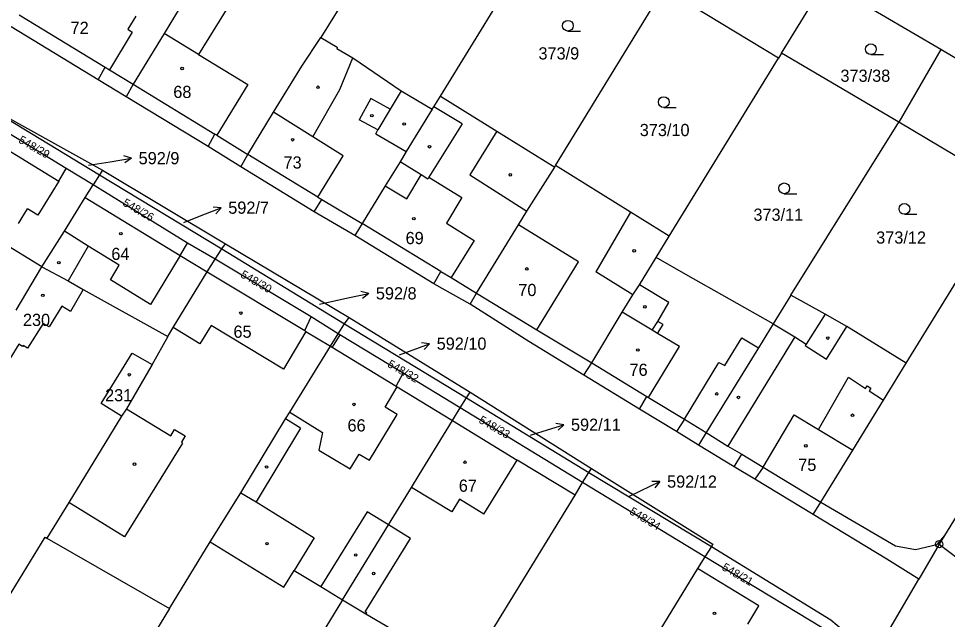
# Model space of a CAD drawing. Extents: x -758582 to -751794, y -998770 to -994350.
# Drawn here: x -754377.8 to -754248.1, y -997016.7 to -996932.8 of the extents above; entities that cross this region are included whole.
import ezdxf

# ---------------------------------------------------------------- set-up
doc = ezdxf.new("R2010")
doc.units = 0
for name, color, linetype in [('Hranice parcel', 7, 'Continuous'), ('Parcelní čísla', 7, 'Continuous'), ('Pop  PČ popisy', 7, 'Continuous'), ('Vnitřní kresba', 7, 'Continuous'), ('Značky bodu BP', 7, 'Continuous'), ('Značky budov', 7, 'Continuous'), ('Značky kultur', 7, 'Continuous')]:
    doc.layers.add(name, color=color, linetype=linetype)

msp = doc.modelspace()

# ---------------------------------------------------------------- linework, layer by layer
at = {"layer": 'Hranice parcel'}
for p, q in [((-754318.92, -996943.63), (-754303.3, -996918.26)), ((-754271.31, -996937.63), (-754265.19, -996927.65)), ((-754249.07, -996937.1), (-754265.19, -996927.65)), ((-754302.83, -996953.32), (-754287.72, -996928.63)), ((-754271.74, -996938.33), (-754287.72, -996928.63)), ((-754249.07, -996937.1), (-754254.94, -996947.27)), ((-754232.94, -996946.73), (-754249.07, -996937.1)), ((-754286.99, -996963.15), (-754271.74, -996938.33)), ((-754271.31, -996937.63), (-754271.74, -996938.33)), ((-754254.94, -996947.27), (-754271.31, -996937.63)), ((-754383.67, -996944.19), (-754366.1, -996953.94)), ((-754383.67, -996944.19), (-754366.52, -996954.61)), ((-754269.98, -996971.41), (-754254.94, -996947.27)), ((-754239.04, -996956.72), (-754254.94, -996947.27)), ((-754366.1, -996953.94), (-754366.52, -996954.61)), ((-754366.1, -996953.94), (-754348.94, -996964.22)), ((-754302.96, -996953.53), (-754302.83, -996953.32)), ((-754366.52, -996954.61), (-754367.41, -996956.01)), ((-754366.52, -996954.61), (-754349.44, -996964.96)), ((-754253.88, -996980.88), (-754239.04, -996956.72)), ((-754288.82, -996966.16), (-754286.99, -996963.15)), ((-754349.44, -996964.96), (-754348.94, -996964.22)), ((-754348.94, -996964.22), (-754331.64, -996974.52)), ((-754350.35, -996966.4), (-754349.44, -996964.96)), ((-754349.44, -996964.96), (-754332.29, -996975.4)), ((-754378.16, -996973.49), (-754374.58, -996967.43)), ((-754368.79, -996970.6), (-754356.99, -996977.19)), ((-754269.98, -996971.41), (-754272.44, -996975.39)), ((-754332.29, -996975.4), (-754331.64, -996974.52)), ((-754331.64, -996974.52), (-754314.77, -996984.96)), ((-754333.17, -996976.81), (-754332.29, -996975.4)), ((-754332.29, -996975.4), (-754315.29, -996985.75)), ((-754356.99, -996977.19), (-754359.18, -996981.08)), ((-754315.29, -996985.75), (-754314.77, -996984.96)), ((-754314.77, -996984.96), (-754297.84, -996995.61)), ((-754316.16, -996987.15), (-754315.29, -996985.75)), ((-754315.29, -996985.75), (-754298.18, -996996.15)), ((-754299.06, -996997.55), (-754316.16, -996987.15)), ((-754298.18, -996996.15), (-754297.84, -996995.61)), ((-754299.06, -996997.55), (-754298.18, -996996.15)), ((-754298.18, -996996.15), (-754281.08, -997006.49)), ((-754281.98, -997007.92), (-754299.06, -996997.55)), ((-754373.87, -997005.32), (-754356.72, -997015.17)), ((-754356.72, -997015.17), (-754351.05, -997005.83)), ((-754281.08, -997006.49), (-754281.98, -997007.92)), ((-754258.68, -997022.29), (-754252.12, -997011.03)), ((-754332.57, -997013.92), (-754336.66, -997020.59)), ((-754356.72, -997015.17), (-754373.8, -997042.91))]:
    msp.add_line(p, q, dxfattribs=at)
for points in [[(-754323.36, -996915.29), (-754327.65, -996922.3), (-754327.53, -996922.34), (-754335.61, -996935.42)], [(-754345.53, -996915.8), (-754345.9, -996916.39), (-754346.91, -996918.02), (-754347.35, -996918.73), (-754349.19, -996921.79), (-754355.4, -996931.43), (-754357.5, -996934.88), (-754361.81, -996941.97), (-754362.79, -996943.71)], [(-754362.79, -996943.71), (-754366.69, -996941.33), (-754378.83, -996933.97)], [(-754346.77, -996953.49), (-754345.82, -996951.75), (-754342.21, -996945.87), (-754338.26, -996939.44), (-754335.61, -996935.42)], [(-754335.61, -996935.42), (-754333.31, -996936.79), (-754333.39, -996936.95), (-754331.15, -996938.27), (-754324.4, -996942.87), (-754320.06, -996945.44)], [(-754346.77, -996953.49), (-754351.36, -996950.67), (-754362.79, -996943.71)], [(-754320.06, -996945.44), (-754319.82, -996945.1), (-754318.92, -996943.63)], [(-754318.92, -996943.63), (-754311.02, -996948.53), (-754302.96, -996953.53)], [(-754367.41, -996956.01), (-754371.18, -996953.71), (-754384.54, -996945.57)], [(-754320.06, -996945.44), (-754323.71, -996951.35), (-754324.53, -996952.81), (-754326.63, -996956.13), (-754329.83, -996961.39), (-754330.85, -996963.1)], [(-754330.85, -996963.1), (-754336.52, -996959.75), (-754346.77, -996953.49)], [(-754314.75, -996972.65), (-754313.87, -996971.12), (-754308, -996961.6), (-754306.83, -996959.7), (-754302.96, -996953.53)], [(-754286.99, -996963.15), (-754292.38, -996959.82), (-754302.83, -996953.32)], [(-754218.11, -996955.35), (-754218.17, -996955.44), (-754248.54, -997004.94), (-754249.29, -997006.16), (-754252.12, -997011.03)], [(-754374.58, -996967.43), (-754371.38, -996962.49), (-754368.51, -996957.75), (-754367.41, -996956.01)], [(-754350.35, -996966.4), (-754354.23, -996964.15), (-754367.41, -996956.01)], [(-754314.75, -996972.65), (-754319.85, -996969.81), (-754330.85, -996963.1)], [(-754356.99, -996977.19), (-754356.24, -996975.93), (-754351.46, -996968.17), (-754350.35, -996966.4)], [(-754333.17, -996976.81), (-754336.96, -996974.44), (-754350.35, -996966.4)], [(-754298.88, -996982.59), (-754297.8, -996980.84), (-754293.55, -996973.77), (-754292.06, -996971.34), (-754291.12, -996969.95), (-754288.82, -996966.16)], [(-754272.44, -996975.39), (-754284.67, -996968.5), (-754288.82, -996966.16)], [(-754374.58, -996967.43), (-754370.89, -996969.4), (-754368.79, -996970.6)], [(-754368.79, -996970.6), (-754370.57, -996973.68), (-754371.79, -996972.96), (-754373.55, -996975.81), (-754374.38, -996975.35), (-754376.57, -996978.82), (-754377.19, -996978.44), (-754377.27, -996978.55), (-754377.78, -996978.26), (-754379.02, -996980.29), (-754381.39, -996978.8)], [(-754253.88, -996980.88), (-754262.19, -996975.76), (-754265.19, -996974.04), (-754269.98, -996971.41)], [(-754298.88, -996982.59), (-754306.59, -996977.86), (-754314.75, -996972.65)], [(-754272.44, -996975.39), (-754274.53, -996978.77), (-754281.81, -996990.6), (-754282.89, -996992.33)], [(-754351.05, -997005.83), (-754346.8, -996999), (-754340.55, -996988.67), (-754339.93, -996987.73), (-754334.25, -996978.53), (-754333.17, -996976.81)], [(-754316.16, -996987.15), (-754324.11, -996982.3), (-754332.95, -996976.93), (-754333.17, -996976.81)], [(-754363.43, -996988.3), (-754366.29, -996986.52), (-754361.96, -996979.49), (-754359.18, -996981.08)], [(-754359.18, -996981.08), (-754362.74, -996987.29), (-754363.43, -996988.3)], [(-754266.86, -997002.01), (-754265.79, -997000.29), (-754261.34, -996993.04), (-754257.07, -996986.08), (-754253.88, -996980.88)], [(-754282.89, -996992.33), (-754285.94, -996990.45), (-754291.13, -996987.3), (-754298.88, -996982.59)], [(-754332.57, -997013.92), (-754326.17, -997003.48), (-754322.94, -996998.24), (-754321.9, -996996.49), (-754317.23, -996988.89), (-754316.16, -996987.15)], [(-754363.43, -996988.3), (-754370.81, -997000.35), (-754373.87, -997005.32)], [(-754266.86, -997002.01), (-754275.01, -996997.08), (-754277.91, -996995.35), (-754282.89, -996992.33)], [(-754297.84, -996995.61), (-754280.88, -997006.15), (-754281.08, -997006.49)], [(-754319.52, -997030.98), (-754300.11, -996999.31), (-754299.06, -996997.55)], [(-754252.12, -997011.03), (-754256.61, -997008.28), (-754266.86, -997002.01)], [(-754391.03, -997032.84), (-754374.11, -997005.21), (-754373.87, -997005.32)], [(-754351.05, -997005.83), (-754340.78, -997012.16), (-754339.33, -997009.82), (-754335.6, -997012.08), (-754332.57, -997013.92)], [(-754281.08, -997006.49), (-754264.39, -997016.71), (-754260.86, -997019.73), (-754258.68, -997022.29)], [(-754281.98, -997007.92), (-754283.01, -997009.56), (-754288.27, -997018.16), (-754295.28, -997029.61), (-754299.99, -997037.3), (-754300.15, -997037.64), (-754303.11, -997042.42), (-754306.17, -997047.33)], [(-754260.55, -997025.5), (-754261.83, -997020.13), (-754281.98, -997007.92)]]:
    msp.add_lwpolyline(points, dxfattribs=at)
at = {"layer": 'Pop  PČ popisy'}
for p, q in [((-754368.07, -996953.27), (-754365.01, -996952.77)), ((-754365.01, -996952.77), (-754362.05, -996952.3)), ((-754362.05, -996952.3), (-754363.11, -996951.96)), ((-754362.05, -996952.3), (-754362.96, -996952.95)), ((-754352.33, -996960.29), (-754349.53, -996959.21)), ((-754349.53, -996959.21), (-754350.64, -996959.11)), ((-754349.53, -996959.21), (-754350.28, -996960.04)), ((-754354.76, -996961.24), (-754352.33, -996960.29)), ((-754331.86, -996971.79), (-754328.93, -996971.17)), ((-754328.93, -996971.17), (-754330.01, -996970.88)), ((-754328.93, -996971.17), (-754329.8, -996971.86)), ((-754335.78, -996972.64), (-754331.86, -996971.79)), ((-754323.25, -996979.22), (-754320.43, -996978.19)), ((-754320.43, -996978.19), (-754321.54, -996978.07)), ((-754320.43, -996978.19), (-754321.2, -996979.01)), ((-754324.62, -996979.73), (-754323.25, -996979.22)), ((-754301.69, -996989.49), (-754302.79, -996989.31)), ((-754306.36, -996990.93), (-754304.56, -996990.37)), ((-754304.56, -996990.37), (-754301.69, -996989.49)), ((-754301.69, -996989.49), (-754302.5, -996990.26)), ((-754290.98, -996998.73), (-754288.28, -996997.41)), ((-754288.28, -996997.41), (-754289.4, -996997.4)), ((-754288.28, -996997.41), (-754288.96, -996998.3)), ((-754292.51, -996999.46), (-754290.98, -996998.73))]:
    msp.add_line(p, q, dxfattribs=at)
at = {"layer": 'Vnitřní kresba'}
for p, q in [((-754342.24, -996920.87), (-754352.68, -996937.8)), ((-754377.74, -996932.26), (-754365.71, -996939.59)), ((-754361.44, -996932.48), (-754362.56, -996934.29)), ((-754361.94, -996934.68), (-754365.13, -996939.94)), ((-754362.56, -996934.29), (-754361.94, -996934.68)), ((-754352.68, -996937.8), (-754357.5, -996934.88)), ((-754352.68, -996937.8), (-754345.79, -996941.98)), ((-754332.94, -996942.68), (-754331.15, -996938.27)), ((-754366.69, -996941.33), (-754365.71, -996939.59)), ((-754365.71, -996939.59), (-754365.13, -996939.94)), ((-754365.13, -996939.94), (-754361.81, -996941.97)), ((-754361.81, -996941.97), (-754350.41, -996948.91)), ((-754345.79, -996941.98), (-754350.15, -996949.06)), ((-754336.71, -996949.31), (-754332.94, -996942.68)), ((-754328.64, -996943.96), (-754330.25, -996946.91)), ((-754325.93, -996945.45), (-754328.64, -996943.96)), ((-754324.4, -996942.87), (-754325.93, -996945.45)), ((-754315.9, -996947.51), (-754319.82, -996945.1)), ((-754336.71, -996949.31), (-754342.21, -996945.87)), ((-754325.93, -996945.45), (-754327.65, -996948.34)), ((-754385.57, -996947.29), (-754372.18, -996955.49)), ((-754327.65, -996948.34), (-754330.25, -996946.91)), ((-754315.9, -996947.51), (-754320.54, -996954.93)), ((-754351.36, -996950.67), (-754350.41, -996948.91)), ((-754350.15, -996949.06), (-754350.41, -996948.91)), ((-754350.15, -996949.06), (-754345.82, -996951.75)), ((-754327.95, -996948.87), (-754327.65, -996948.34)), ((-754327.95, -996948.87), (-754323.71, -996951.35)), ((-754311.02, -996948.53), (-754314.83, -996954.63)), ((-754332.49, -996951.95), (-754336.71, -996949.31)), ((-754336.02, -996957.71), (-754345.82, -996951.75)), ((-754336.02, -996957.71), (-754332.49, -996951.95)), ((-754321.62, -996954.61), (-754324.53, -996952.81)), ((-754372.18, -996955.49), (-754371.18, -996953.71)), ((-754372.18, -996955.49), (-754375.14, -996960.23)), ((-754323.61, -996957.97), (-754321.62, -996954.61)), ((-754320.68, -996955.2), (-754321.62, -996954.61)), ((-754320.54, -996954.93), (-754320.68, -996955.2)), ((-754320.54, -996954.93), (-754315.93, -996957.76)), ((-754314.83, -996954.63), (-754306.83, -996959.7)), ((-754326.63, -996956.13), (-754323.61, -996957.97)), ((-754368.51, -996957.75), (-754355.23, -996965.86)), ((-754336.52, -996959.75), (-754335.48, -996958.05)), ((-754336.02, -996957.71), (-754335.48, -996958.05)), ((-754335.48, -996958.05), (-754329.83, -996961.39)), ((-754315.93, -996957.76), (-754318.06, -996961.34)), ((-754377.84, -996961.41), (-754376.57, -996959.34)), ((-754375.14, -996960.23), (-754376.57, -996959.34)), ((-754292.38, -996959.82), (-754297.22, -996968.13)), ((-754318.84, -996968.08), (-754329.83, -996961.39)), ((-754318.06, -996961.34), (-754314.2, -996963.76)), ((-754299.63, -996966.75), (-754308, -996961.6)), ((-754368.08, -996964.55), (-754371.38, -996962.49)), ((-754374.58, -996967.43), (-754380.5, -996963.81)), ((-754368.08, -996964.55), (-754370.89, -996969.4)), ((-754363.75, -996967.22), (-754368.08, -996964.55)), ((-754355.23, -996965.86), (-754354.23, -996964.15)), ((-754314.2, -996963.76), (-754317.42, -996968.93)), ((-754355.23, -996965.86), (-754359.37, -996972.73)), ((-754355.23, -996965.86), (-754351.46, -996968.17)), ((-754364.97, -996969.25), (-754363.75, -996967.22)), ((-754305.47, -996976.26), (-754299.63, -996966.75)), ((-754351.46, -996968.17), (-754337.86, -996976.34)), ((-754319.85, -996969.81), (-754318.84, -996968.08)), ((-754318.84, -996968.08), (-754317.42, -996968.93)), ((-754292.06, -996971.34), (-754297.22, -996968.13)), ((-754359.37, -996972.73), (-754364.97, -996969.25)), ((-754317.42, -996968.93), (-754313.87, -996971.12)), ((-754287.01, -996972.42), (-754291.12, -996969.95)), ((-754313.87, -996971.12), (-754305.47, -996976.26)), ((-754288.58, -996975.07), (-754287.01, -996972.42)), ((-754289.34, -996976.31), (-754293.55, -996973.77)), ((-754337.86, -996976.34), (-754336.96, -996974.44)), ((-754289.34, -996976.31), (-754288.58, -996975.07)), ((-754287.83, -996975.51), (-754288.58, -996975.07)), ((-754265.19, -996974.04), (-754267.87, -996978.24)), ((-754352.49, -996978.22), (-754356.24, -996975.93)), ((-754350.92, -996975.66), (-754352.49, -996978.22)), ((-754340.84, -996981.73), (-754350.92, -996975.66)), ((-754337.86, -996976.34), (-754337.69, -996976.49)), ((-754305.47, -996976.26), (-754297.8, -996980.84)), ((-754288.6, -996976.74), (-754289.34, -996976.31)), ((-754288.6, -996976.74), (-754287.83, -996975.51)), ((-754272.44, -996975.39), (-754269.43, -996977.23)), ((-754265.04, -996980.36), (-754262.19, -996975.76)), ((-754337.69, -996976.49), (-754340.84, -996981.73)), ((-754337.69, -996976.49), (-754334.25, -996978.53)), ((-754332.95, -996976.93), (-754334.03, -996978.66)), ((-754285.55, -996978.59), (-754288.6, -996976.74)), ((-754279.2, -996981.23), (-754276.86, -996977.36)), ((-754269.43, -996977.23), (-754278.81, -996992.47)), ((-754276.86, -996977.36), (-754274.53, -996978.77)), ((-754269.43, -996977.23), (-754267.87, -996978.24)), ((-754334.25, -996978.53), (-754334.03, -996978.66)), ((-754334.03, -996978.66), (-754325.09, -996984.1)), ((-754289.87, -996985.71), (-754285.55, -996978.59)), ((-754267.87, -996978.24), (-754268, -996978.45)), ((-754268, -996978.45), (-754265.04, -996980.36)), ((-754297.8, -996980.84), (-754290.08, -996985.57)), ((-754284.85, -996988.7), (-754280.04, -996980.8)), ((-754280.04, -996980.8), (-754279.2, -996981.23)), ((-754325.09, -996984.1), (-754324.11, -996982.3)), ((-754266.14, -996990.16), (-754261.95, -996982.86)), ((-754261.95, -996982.86), (-754259.57, -996984.42)), ((-754326.65, -996987.03), (-754324.95, -996984.19)), ((-754325.09, -996984.1), (-754324.95, -996984.19)), ((-754324.95, -996984.19), (-754317.23, -996988.89)), ((-754259.57, -996984.42), (-754259.34, -996984.07)), ((-754259.34, -996984.07), (-754258.83, -996984.41)), ((-754258.83, -996984.41), (-754259.07, -996984.76)), ((-754259.07, -996984.76), (-754257.07, -996986.08)), ((-754291.13, -996987.3), (-754290.08, -996985.57)), ((-754290.08, -996985.57), (-754289.87, -996985.71)), ((-754289.87, -996985.71), (-754284.85, -996988.7)), ((-754362.74, -996987.29), (-754356.57, -996991.05)), ((-754339.93, -996987.73), (-754335.4, -996990.56)), ((-754328.84, -996994.44), (-754324.96, -996988.05)), ((-754324.96, -996988.05), (-754326.65, -996987.03)), ((-754273.86, -996995.43), (-754269.55, -996988.11)), ((-754269.55, -996988.11), (-754266.14, -996990.16)), ((-754338.45, -996989.98), (-754340.55, -996988.67)), ((-754317.23, -996988.89), (-754308.21, -996994.45)), ((-754284.85, -996988.7), (-754285.94, -996990.45)), ((-754284.85, -996988.7), (-754281.81, -996990.6)), ((-754356.57, -996991.05), (-754356.02, -996990.18)), ((-754356.02, -996990.18), (-754354.53, -996991.03)), ((-754338.45, -996989.98), (-754344.66, -997000.26)), ((-754335.4, -996990.56), (-754335.9, -996993.06)), ((-754281.81, -996990.6), (-754278.81, -996992.47)), ((-754266.14, -996990.16), (-754261.34, -996993.04)), ((-754354.94, -996992.05), (-754363.01, -997005.14)), ((-754354.53, -996991.03), (-754355.07, -996991.94)), ((-754355.07, -996991.94), (-754354.94, -996992.05)), ((-754335.9, -996993.06), (-754331.52, -996995.67)), ((-754278.81, -996992.47), (-754276.85, -996993.6)), ((-754331.52, -996995.67), (-754330.26, -996993.62)), ((-754330.26, -996993.62), (-754328.84, -996994.44)), ((-754312.84, -997001.99), (-754308.21, -996994.45)), ((-754300.11, -996999.31), (-754308.21, -996994.45)), ((-754277.91, -996995.35), (-754276.85, -996993.6)), ((-754276.85, -996993.6), (-754273.86, -996995.43)), ((-754273.86, -996995.43), (-754275.01, -996997.08)), ((-754273.86, -996995.43), (-754265.79, -997000.29)), ((-754317.31, -997001.66), (-754322.94, -996998.24)), ((-754346.8, -996999), (-754344.66, -997000.26)), ((-754363.01, -997005.14), (-754370.81, -997000.35)), ((-754344.66, -997000.26), (-754336.54, -997005.3)), ((-754316.27, -996999.89), (-754317.31, -997001.66)), ((-754312.84, -997001.99), (-754316.27, -996999.89)), ((-754265.79, -997000.29), (-754255.4, -997006.4)), ((-754329.14, -997001.67), (-754335.6, -997012.08)), ((-754326.17, -997003.48), (-754329.14, -997001.67)), ((-754323.11, -997005.37), (-754326.17, -997003.48)), ((-754248.54, -997004.94), (-754249.61, -997006.22)), ((-754336.54, -997005.3), (-754339.33, -997009.82)), ((-754329.44, -997015.59), (-754323.11, -997005.37)), ((-754252.57, -997006.91), (-754249.61, -997006.22)), ((-754249.29, -997006.16), (-754246.61, -997008.22)), ((-754255.4, -997006.4), (-754252.57, -997006.91)), ((-754274.48, -997014.78), (-754283.01, -997009.56)), ((-754332.57, -997013.92), (-754329.32, -997015.89)), ((-754276.01, -997017.34), (-754274.48, -997014.78)), ((-754329.19, -997015.74), (-754329.44, -997015.59)), ((-754329.19, -997015.74), (-754329.32, -997015.89)), ((-754329.32, -997015.89), (-754318.78, -997022.05))]:
    msp.add_line(p, q, dxfattribs=at)
at = {"layer": 'Značky bodu BP'}
for radius in [0.5, 0.0303]:
    msp.add_circle((-754249.29, -997006.16), radius, dxfattribs=at)
at = {"layer": 'Značky budov'}
for centre in [(-754354.98, -996939.76), (-754336.01, -996942.38), (-754328.49, -996946.35), (-754323.98, -996947.51), (-754339.55, -996949.71), (-754320.44, -996950.69), (-754309.16, -996954.61), (-754322.63, -996960.72), (-754363.53, -996962.82), (-754291.87, -996965.22), (-754372.19, -996966.86), (-754306.86, -996967.74), (-754374.42, -996971.44), (-754346.77, -996973.91), (-754290.37, -996973.04), (-754264.84, -996977.4), (-754291.35, -996979.06), (-754362.35, -996982.52), (-754280.35, -996985.19), (-754277.31, -996985.68), (-754330.99, -996986.66), (-754261.38, -996988.17), (-754267.9, -996992.44), (-754315.48, -996994.73), (-754361.63, -996995), (-754343.19, -996995.4), (-754343.12, -997006.1), (-754330.74, -997007.67), (-754328.24, -997010.26), (-754280.65, -997015.83)]:
    msp.add_circle(centre, 0.175, dxfattribs=at)
at = {"layer": 'Značky kultur'}
for p, q in [((-754301.12, -996934.54), (-754299.37, -996934.54)), ((-754258.82, -996937.82), (-754257.07, -996937.82)), ((-754287.74, -996945.2), (-754285.99, -996945.2)), ((-754270.92, -996957.24), (-754269.17, -996957.24)), ((-754254.14, -996960.11), (-754252.39, -996960.11))]:
    msp.add_line(p, q, dxfattribs=at)
for centre in [(-754301.12, -996933.79), (-754258.82, -996937.07), (-754287.74, -996944.45), (-754270.92, -996956.49), (-754254.14, -996959.36)]:
    msp.add_circle(centre, 0.75, dxfattribs=at)

# ---------------------------------------------------------------- texts
at = {"layer": 'Parcelní čísla'}
for s, p in [('72', (-754370.55, -996934.93)), ('373/9', (-754305.23, -996938.5)), ('373/38', (-754263.07, -996941.62)), ('68', (-754356.21, -996943.88)), ('373/10', (-754291.09, -996949.2)), ('592/9', (-754361.05, -996953.13)), ('73', (-754340.82, -996953.73)), ('592/7', (-754348.54, -996960.04)), ('373/11', (-754275.22, -996961.02)), ('69', (-754323.78, -996964.28)), ('373/12', (-754258.08, -996964.21)), ('64', (-754364.86, -996966.49)), ('70', (-754308.04, -996971.53)), ('592/8', (-754327.93, -996972)), ('230', (-754377.2, -996975.71)), ('65', (-754347.81, -996977.35)), ('592/10', (-754319.44, -996979.02)), ('76', (-754292.52, -996982.67)), ('231', (-754365.73, -996986.22)), ('66', (-754331.89, -996990.43)), ('592/11', (-754300.69, -996990.34)), ('75', (-754268.96, -996995.95)), ('67', (-754316.35, -996998.85)), ('592/12', (-754287.27, -996998.28))]:
    msp.add_text(s, height=1.7, dxfattribs=at).set_placement(p)
for s, rotation, p in [('548/29', 330, (-754377.92, -996950.05)), ('548/26', 330, (-754363.38, -996958.82)), ('548/30', 330, (-754346.92, -996968.84)), ('548/32', 330, (-754326.41, -996981.34)), ('548/33', 330, (-754313.66, -996989.15)), ('548/34', 329, (-754292.62, -997001.89)), ('548/21', 330, (-754279.71, -997009.7))]:
    msp.add_text(s, height=1.14, rotation=rotation, dxfattribs=at).set_placement(p)

doc.saveas('drawing.dxf')
